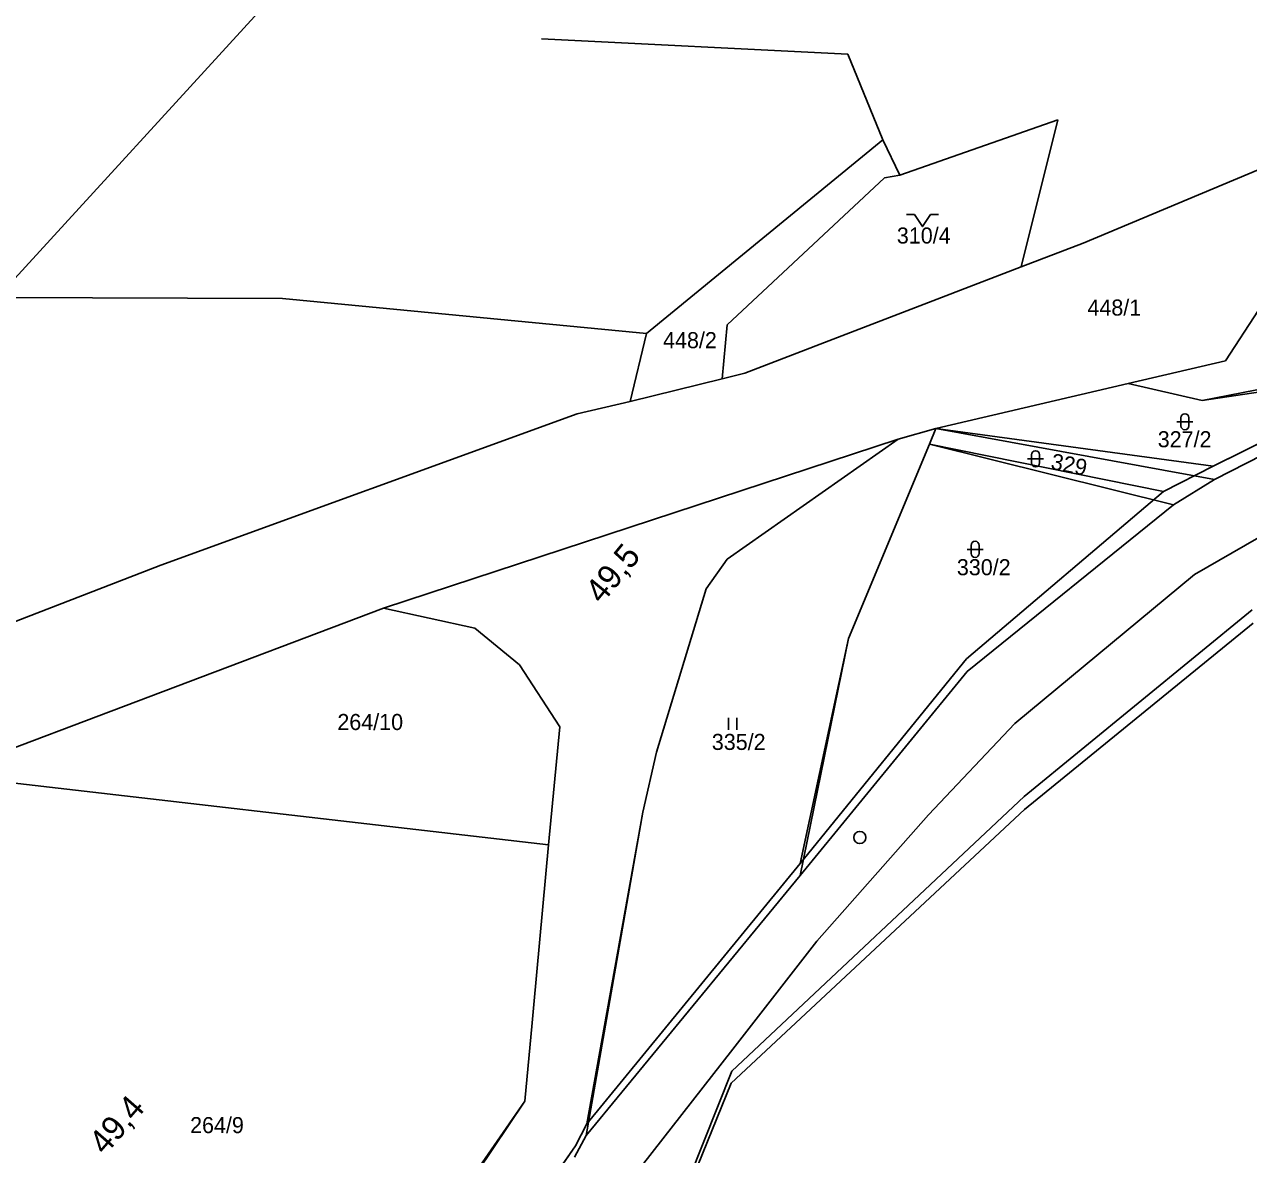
# Model space of a CAD drawing. Extents: x -678683 to -677755, y -1006946 to -1005971.
# Drawn here: x -678311.9 to -678159.6, y -1006450.6 to -1006309.9 of the extents above; entities that cross this region are included whole.
import ezdxf

# ---------------------------------------------------------------- set-up
doc = ezdxf.new("R2010")
doc.units = 0
for name, color, linetype in [('I_2_4_předběžný_vykres - SŽDC', 7, 'Continuous'), ('kilometráž - Vrstva 7', 7, 'Continuous'), ('koor - SSZT_nové', 7, 'Continuous'), ('MapaKN - Mladejov+Strelec_dosavani+nova_situace - Vrstva 1', 7, 'Continuous'), ('MapaKN - Mladejov+Strelec_dosavani+nova_situace - Vrstva 11', 7, 'Continuous'), ('MapaKN - Mladejov+Strelec_dosavani+nova_situace - Vrstva 18', 7, 'Continuous'), ('MapaKN - Mladejov+Strelec_dosavani+nova_situace - Vrstva 25', 7, 'Continuous'), ('MapaKN - původní vrstava 1', 7, 'Continuous'), ('ramy - Sekce lichá', 7, 'Continuous')]:
    doc.layers.add(name, color=color, linetype=linetype)

msp = doc.modelspace()

# ---------------------------------------------------------------- linework, layer by layer
at = {"layer": 'I_2_4_předběžný_vykres - SŽDC'}
for p, q in [((-678135.76, -1006350.92), (-678163.98, -1006364.86)), ((-678163.98, -1006364.86), (-678170.18, -1006368.03)), ((-678170.18, -1006368.03), (-678194.69, -1006388.87)), ((-678187.52, -1006406.01), (-678159.12, -1006382.74)), ((-678194.69, -1006388.87), (-678215.4, -1006414.33)), ((-678223.89, -1006440.18), (-678187.52, -1006406.01)), ((-678215.4, -1006414.33), (-678241.94, -1006446.76)), ((-678229.19, -1006453.42), (-678223.89, -1006440.18)), ((-678241.94, -1006446.76), (-678243.35, -1006449.47)), ((-678243.35, -1006449.47), (-678259.32, -1006472.44))]:
    msp.add_line(p, q, dxfattribs=at)
at = {"layer": 'kilometráž - Vrstva 7'}
msp.add_circle((-678207.97, -1006411.1), 0.75, dxfattribs=at)
at = {"layer": 'koor - SSZT_nové'}
for points in [[(-678199.43, -1006408.27), (-678188.69, -1006396.92), (-678166.33, -1006378.36), (-678141.21, -1006363.9), (-678122.02, -1006355.42), (-678102.99, -1006349.89), (-678082.69, -1006345.92), (-678069.35, -1006344.3), (-678054.02, -1006343.3), (-678039.76, -1006343.69), (-678028.1, -1006343.37), (-677988.11, -1006347.69), (-677946.88, -1006353.16), (-677923.77, -1006355.85)], [(-678276.52, -1006503.93), (-678257.42, -1006480.58), (-678238.83, -1006456.75), (-678223.79, -1006437.46), (-678213.31, -1006424.02), (-678199.43, -1006408.27)]]:
    msp.add_lwpolyline(points, dxfattribs=at)
at = {"layer": 'MapaKN - Mladejov+Strelec_dosavani+nova_situace - Vrstva 1'}
for points in [[(-678209.48, -1006313.6), (-678247.59, -1006311.68)], [(-678209.48, -1006313.6), (-678205.1, -1006324.25)], [(-678130.46, -1006316.3), (-678180.18, -1006337.1)], [(-678203, -1006328.63), (-678183.32, -1006321.76)], [(-678183.32, -1006321.76), (-678187.9, -1006340.07)], [(-678234.53, -1006348.36), (-678205.1, -1006324.25)], [(-678205.1, -1006324.25), (-678203, -1006328.63)], [(-678204.88, -1006328.99), (-678224.49, -1006347.26)], [(-678203, -1006328.63), (-678204.88, -1006328.99)], [(-678180.18, -1006337.1), (-678187.9, -1006340.07)], [(-678187.9, -1006340.07), (-678222.28, -1006353.31)], [(-678315.33, -1006343.88), (-678279.85, -1006344.02)], [(-678279.85, -1006344.02), (-678234.53, -1006348.36)], [(-678158.36, -1006345.46), (-678162.46, -1006351.78)], [(-678224.49, -1006347.26), (-678225.12, -1006354)], [(-678234.53, -1006348.36), (-678236.56, -1006356.81)], [(-678174.55, -1006354.6), (-678162.46, -1006351.78)], [(-678225.12, -1006354), (-678236.56, -1006356.81)], [(-678222.28, -1006353.31), (-678225.12, -1006354)], [(-678198.51, -1006360.2), (-678174.55, -1006354.6)], [(-678174.55, -1006354.6), (-678165.35, -1006356.69)], [(-678236.56, -1006356.81), (-678243.14, -1006358.35)], [(-678243.14, -1006358.35), (-678294.96, -1006377.2)], [(-678203.18, -1006361.53), (-678198.51, -1006360.2)], [(-678198.51, -1006360.2), (-678199.31, -1006362.12)], [(-678267.26, -1006382.54), (-678203.18, -1006361.53)], [(-678203.18, -1006361.53), (-678224.47, -1006376.45)], [(-678199.31, -1006362.12), (-678209.39, -1006386.33)], [(-678294.96, -1006377.2), (-678336.38, -1006393.2)], [(-678224.47, -1006376.45), (-678227.09, -1006380.13)], [(-678227.09, -1006380.13), (-678233.26, -1006400.47)], [(-678267.26, -1006382.54), (-678322.15, -1006403.3)], [(-678255.9, -1006385.05), (-678267.26, -1006382.54)], [(-678250.31, -1006389.6), (-678255.9, -1006385.05)], [(-678245.33, -1006397.33), (-678250.31, -1006389.6)], [(-678246.7, -1006412.02), (-678245.33, -1006397.33)], [(-678233.26, -1006400.47), (-678234.96, -1006407.96)], [(-678246.7, -1006412.02), (-678322.15, -1006403.3)], [(-678248.56, -1006431.87), (-678246.7, -1006412.02)], [(-678248.77, -1006434.15), (-678248.56, -1006431.87)], [(-678249.68, -1006443.91), (-678248.77, -1006434.15)]]:
    msp.add_lwpolyline(points, dxfattribs=at)
at = {"layer": 'MapaKN - Mladejov+Strelec_dosavani+nova_situace - Vrstva 11'}
msp.add_line((-678215.4, -1006414.33), (-678209.39, -1006386.33), dxfattribs=at)
for points in [[(-678135.76, -1006350.92), (-678165.35, -1006356.69)], [(-678163.98, -1006364.86), (-678135.76, -1006350.92)], [(-678163.98, -1006364.86), (-678198.51, -1006360.2)], [(-678170.18, -1006368.03), (-678199.31, -1006362.12)], [(-678170.18, -1006368.03), (-678163.98, -1006364.86)], [(-678194.69, -1006388.87), (-678170.18, -1006368.03)], [(-678159.12, -1006382.74), (-678187.52, -1006406.01)], [(-678215.4, -1006414.33), (-678194.69, -1006388.87)], [(-678187.52, -1006406.01), (-678223.89, -1006440.18)], [(-678241.94, -1006446.76), (-678234.96, -1006407.96)], [(-678241.94, -1006446.76), (-678215.4, -1006414.33)], [(-678223.89, -1006440.18), (-678229.19, -1006453.42)], [(-678272.96, -1006477.58), (-678249.68, -1006443.91)], [(-678243.35, -1006449.47), (-678241.94, -1006446.76)], [(-678259.32, -1006472.44), (-678243.35, -1006449.47)]]:
    msp.add_lwpolyline(points, dxfattribs=at)
at = {"layer": 'MapaKN - Mladejov+Strelec_dosavani+nova_situace - Vrstva 25'}
for points in [[(-678202.17, -1006333.56), (-678201.17, -1006333.56), (-678200.17, -1006335.06), (-678199.17, -1006333.56), (-678198.17, -1006333.56)], [(-678168.01, -1006359.85), (-678168.01, -1006358.85)], [(-678167.01, -1006358.85), (-678167.01, -1006359.85)], [(-678168.51, -1006359.35), (-678166.51, -1006359.35)], [(-678186.6, -1006364.46), (-678186.6, -1006363.46)], [(-678185.6, -1006363.46), (-678185.6, -1006364.46)], [(-678187.1, -1006363.96), (-678185.1, -1006363.96)], [(-678194.62, -1006375.23), (-678192.62, -1006375.23)], [(-678194.12, -1006375.73), (-678194.12, -1006374.73)], [(-678193.12, -1006374.73), (-678193.12, -1006375.73)], [(-678224.31, -1006397.71), (-678224.31, -1006396.21)], [(-678223.27, -1006397.71), (-678223.27, -1006396.21)]]:
    msp.add_lwpolyline(points, dxfattribs=at)
for centre, start, end in [((-678167.51, -1006358.85), 0.101, 180.0014), ((-678167.51, -1006359.85), 180.1024, 0.0029), ((-678186.1, -1006363.46), 0.101, 180.0014), ((-678186.1, -1006364.46), 180.1024, 0.0029), ((-678193.62, -1006374.73), 0.101, 180.0014), ((-678193.62, -1006375.73), 180.1024, 0.0029)]:
    msp.add_arc(centre, 0.5, start, end, dxfattribs=at)
at = {"layer": 'MapaKN - původní vrstava 1'}
for points in [[(-678165.35, -1006356.69), (-678136.03, -1006352.33)], [(-678136.03, -1006352.33), (-678163.82, -1006366.54)], [(-678198.51, -1006360.2), (-678163.82, -1006366.54)], [(-678168.94, -1006369.68), (-678199.31, -1006362.12)], [(-678163.82, -1006366.54), (-678168.94, -1006369.68)], [(-678168.94, -1006369.68), (-678194.61, -1006390.45)], [(-678159.02, -1006384.43), (-678187.49, -1006407.61)], [(-678209.39, -1006386.33), (-678215.4, -1006415.84)], [(-678194.61, -1006390.45), (-678215.4, -1006415.84)], [(-678187.49, -1006407.61), (-678223.98, -1006441.66)], [(-678234.96, -1006407.96), (-678242.05, -1006448.18)], [(-678215.4, -1006415.84), (-678242.05, -1006448.18)], [(-678223.98, -1006441.66), (-678229.32, -1006454.88)], [(-678273.17, -1006478.9), (-678249.68, -1006443.91)], [(-678242.05, -1006448.18), (-678243.47, -1006450.89)]]:
    msp.add_lwpolyline(points, dxfattribs=at)
at = {"layer": 'ramy - Sekce lichá'}
msp.add_line((-678399.5, -1006435.89), (-678257.76, -1006280.94), dxfattribs=at)

# ---------------------------------------------------------------- texts
at = {"layer": 'kilometráž - Vrstva 7'}
for s, rotation, p in [('49,5', 50.4282, (-678240.09, -1006382.15)), ('49,4', 48.8843, (-678301.93, -1006450.75))]:
    msp.add_text(s, height=3, rotation=rotation, dxfattribs=at).set_placement(p)
at = {"layer": 'MapaKN - Mladejov+Strelec_dosavani+nova_situace - Vrstva 18'}
for s, p in [('310/4', (-678203.36, -1006337.16)), ('448/1', (-678179.64, -1006346.13)), ('448/2', (-678232.46, -1006350.19)), ('327/2', (-678170.89, -1006362.52)), ('330/2', (-678195.89, -1006378.45)), ('264/10', (-678273, -1006397.72)), ('335/2', (-678226.39, -1006400.2)), ('264/9', (-678291.33, -1006447.9))]:
    msp.add_text(s, height=2, dxfattribs=at).set_placement(p)
msp.add_text('329', height=2, rotation=349.0028, dxfattribs=at).set_placement((-678184.29, -1006365.22))

doc.saveas('drawing.dxf')
